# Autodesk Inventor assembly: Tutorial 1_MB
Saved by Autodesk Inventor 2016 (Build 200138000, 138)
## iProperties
Created: 2015-04
Part Number: Tutorial 1_MB
Document SubType Name: Assembly
Designer: Sandeep
Author: Sandeep
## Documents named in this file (16)
- C:\Autodesk Inventor 2016\c19\MB\FUTABA_SA-S 1\Tutorial 1_MB.iam
- C:\Users\Sandeep\Documents\Inventor\Content Center Files\R2016\en-US\JIS 1176\JIS 1176 M12x40.ipt
- C:\Users\Sandeep\Documents\Inventor\Content Center Files\R2016\en-US\GBA\M-GBA 40x69.ipt
- C:\Autodesk Inventor 2016\c19\MB\FUTABA_SA-S 1\Tutorial 1_MB_SA-SB1.ipt
- C:\Autodesk Inventor 2016\c19\MB\FUTABA_SA-S 1\Tutorial 1_MB_SA-SB2.ipt
- C:\Autodesk Inventor 2016\c19\MB\FUTABA_SA-S 1\Tutorial 1_MB_SA-EP.ipt
- C:\Users\Sandeep\Documents\Inventor\Content Center Files\R2016\en-US\GPA\M-GPA40x217x69.ipt
- C:\Autodesk Inventor 2016\c19\MB\FUTABA_SA-S 1\Tutorial 1_MB_SA-ERP.ipt
- C:\Autodesk Inventor 2016\c19\MB\FUTABA_SA-S 1\Tutorial 1_MB_SA-BCP.ipt
- C:\Users\Sandeep\Documents\Inventor\Content Center Files\R2016\en-US\JIS 1176\JIS 1176 M16x35.ipt
- C:\Autodesk Inventor 2016\c19\MB\FUTABA_SA-S 1\Tutorial 1_MB_RPN.ipt
- C:\Autodesk Inventor 2016\c19\MB\FUTABA_SA-S 1\Tutorial 1_MB_SA-S-AP.ipt
- C:\Autodesk Inventor 2016\c19\MB\FUTABA_SA-S 1\Tutorial 1_MB_SA-S-BP.ipt
- C:\Autodesk Inventor 2016\c19\MB\FUTABA_SA-S 1\Tutorial 1_MB_SA-TCP.ipt
- C:\Autodesk Inventor 2016\c19\MB\FUTABA_SA-S 1\Tutorial 1_MB_SA-SP.ipt
- C:\Users\Sandeep\Documents\Inventor\Content Center Files\R2016\en-US\JIS 1176\JIS 1176 M16x210.ipt
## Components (37 placed, 15 different names)
1. Tutorial 1_MB_SA-SB1:1 — Flush:1, Flush:3, Mate:1, Mate:5
2. Tutorial 1_MB_SA-SB2:2 — Flush:2, Flush:4, Mate:2, Mate:6
3. Tutorial 1_MB_SA-EP:1 — Insert:1, Flush:5, Flush:6, Ejection, Mate:4
4. Tutorial 1_MB_SA-ERP:1 — Insert:7, Flush:7, Flush:8, Mate:4
5. Tutorial 1_MB_SA-BCP:1 — Insert:8, Ejection, Flush:9, Flush:10, Mate:5, Mate:6
6. Tutorial 1_MB_SA-S-AP:1 — Insert:2, Insert:5, Flush:11, Flush:12, Mate:7, PL1, Flush:19
7. Tutorial 1_MB_SA-S-BP:1 — Insert:3, Insert:4, Flush:13, Flush:14, PL1, Mate:9
8. Tutorial 1_MB_SA-TCP:1 — Insert:6, Mate:7, Flush:15, Flush:16
9. Tutorial 1_MB_SA-SP:1 — Mate:1, Mate:2, Flush:17, Flush:18, Mate:9
10. GPA 40x217x69:1 — Insert:3
11. GPA 40x217x69:3
12. JIS 1176 M16x35:1 — Insert:6
13. JIS 1176 M16x35:2
14. JIS 1176 M16x35:3
15. JIS 1176 M16x35:4
16. JIS 1176 M16x35:5
17. JIS 1176 M16x35:6
18. JIS 1176 M12x40:1 — Insert:1
19. JIS 1176 M12x40:2
20. JIS 1176 M12x40:3
21. JIS 1176 M12x40:4
22. JIS 1176 M16x210:1 — Insert:8
23. JIS 1176 M16x210:2
24. JIS 1176 M16x210:3
25. JIS 1176 M16x210:4
26. JIS 1176 M16x210:5
27. JIS 1176 M16x210:6
28. GBA 40x69:1 — Insert:2
29. GBA 40x69:3
30. GPA 40x217x69:2 — Insert:4
31. GPA 40x217x69:4
32. Tutorial 1_MB_RPN:1 — Insert:7
33. Tutorial 1_MB_RPN:2
34. Tutorial 1_MB_RPN:3
35. Tutorial 1_MB_RPN:4
36. GBA 40x69:2 — Insert:5
37. GBA 40x69:4
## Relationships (36: Flush 19, Mate 9, Insert 8)
- Insert:1: Tutorial 1_MB_SA-EP:1 ↔ JIS 1176 M12x40:1
- Insert:2: Tutorial 1_MB_SA-S-AP:1 ↔ GBA 40x69:1
- Insert:3: Tutorial 1_MB_SA-S-BP:1 ↔ GPA 40x217x69:1
- Insert:4: Tutorial 1_MB_SA-S-BP:1 ↔ GPA 40x217x69:2
- Insert:5: Tutorial 1_MB_SA-S-AP:1 ↔ GBA 40x69:2
- Insert:6: Tutorial 1_MB_SA-TCP:1 ↔ JIS 1176 M16x35:1
- Insert:7: Tutorial 1_MB_SA-ERP:1 ↔ Tutorial 1_MB_RPN:1
- Insert:8: Tutorial 1_MB_SA-BCP:1 ↔ JIS 1176 M16x210:1
- Flush:1: Tutorial 1_MB_SA-SB1:1
- Flush:2: Tutorial 1_MB_SA-SB2:2
- Flush:3: Tutorial 1_MB_SA-SB1:1
- Flush:4: Tutorial 1_MB_SA-SB2:2
- Mate:1: Tutorial 1_MB_SA-SB1:1 ↔ Tutorial 1_MB_SA-SP:1
- Mate:2: Tutorial 1_MB_SA-SB2:2 ↔ Tutorial 1_MB_SA-SP:1
- Flush:5: Tutorial 1_MB_SA-EP:1
- Flush:6: Tutorial 1_MB_SA-EP:1
- Ejection [Mate]: Tutorial 1_MB_SA-EP:1 ↔ Tutorial 1_MB_SA-BCP:1
- Flush:7: Tutorial 1_MB_SA-ERP:1
- Flush:8: Tutorial 1_MB_SA-ERP:1
- Mate:4: Tutorial 1_MB_SA-EP:1 ↔ Tutorial 1_MB_SA-ERP:1
- Flush:9: Tutorial 1_MB_SA-BCP:1
- Flush:10: Tutorial 1_MB_SA-BCP:1
- Mate:5: Tutorial 1_MB_SA-SB1:1 ↔ Tutorial 1_MB_SA-BCP:1
- Mate:6: Tutorial 1_MB_SA-SB2:2 ↔ Tutorial 1_MB_SA-BCP:1
- Flush:11: Tutorial 1_MB_SA-S-AP:1
- Flush:12: Tutorial 1_MB_SA-S-AP:1
- Mate:7: Tutorial 1_MB_SA-S-AP:1 ↔ Tutorial 1_MB_SA-TCP:1
- Flush:13: Tutorial 1_MB_SA-S-BP:1
- Flush:14: Tutorial 1_MB_SA-S-BP:1
- PL1 [Mate]: Tutorial 1_MB_SA-S-AP:1 ↔ Tutorial 1_MB_SA-S-BP:1
- Flush:15: Tutorial 1_MB_SA-TCP:1
- Flush:16: Tutorial 1_MB_SA-TCP:1
- Flush:17: Tutorial 1_MB_SA-SP:1
- Flush:18: Tutorial 1_MB_SA-SP:1
- Mate:9: Tutorial 1_MB_SA-S-BP:1 ↔ Tutorial 1_MB_SA-SP:1
- Flush:19: Tutorial 1_MB_SA-S-AP:1
